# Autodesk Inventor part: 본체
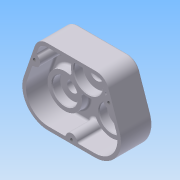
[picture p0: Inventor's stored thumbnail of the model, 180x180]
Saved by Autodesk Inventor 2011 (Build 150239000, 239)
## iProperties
Created: 2014-12
Part Number: 본체
Document SubType Name: Modeling
Designer: SDA24
Density: 2.70923 g/cm^3
Material: 알루미늄-6061
Mass: 613.257 g
Surface Area: 665.191 cm^2
Volume: 226.358 cm^3
Author: SDA24
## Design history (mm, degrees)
sketch "스케치1"
  geometry: L1 (-47, 36)-(47, 36); L2 (0, 46)-(0, -46); L3 (0, 0)-(-32.527, -32.527); L4 (0, 0)-(32.527, -32.527); L5 (-47, 36)-(-66.565, -20.803); L6 (47, 36)-(66.565, -20.803); L7 (-32.527, -68.527)-(32.527, -68.527); A1 r 46 centre (0, 0) between (0, 46) and (0, -46); A2 r 36 centre (-32.527, -32.527) between (-66.565, -20.803) and (-32.527, -68.527); A3 r 36 centre (32.527, -32.527) between (32.527, -68.527) and (66.565, -20.803); 2 further points
  constraints: 14 end point, 8 point on circle, 4 midpoint, 3 centre point, 3 coincident, 2 horizontal, 2 perpendicular, 2 symmetric about line, 2 tangent, 1 point on line, 1 vertical alignment, 2 other
  dimensions: "d1" = 94 distance of L1.start L1.end; "d2" = 36 distance from line of point (0, 0) L1; "d3" = 92 diameter of A1; "d4" = 90 deg angle of L4 L3 (derived); "d5" = 72 diameter of A2
extrude "돌출1" new body sketch "스케치1" distance "d6" = 44; taper "d7" = 0 deg
fillet "모깎기1" dims "d8" = 18
feature "쉘1" dims "d9" = 5
sketch "스케치2"
  geometry: L1 (-27.675, -53.432)-(-12.291, -8.767) reference; L2 (66.689, -94.527)-(1.635, -94.527) reference; L3 (80.615, -8.767)-(95.999, -53.432) reference; L4 (0, 0)-(68.324, 0) reference; L5 (-27.675, -53.432)-(-12.291, -8.767) reference; L6 (66.689, -94.527)-(1.635, -94.527) reference; L7 (80.615, -8.767)-(95.999, -53.432) reference; L8 (0, 0)-(68.324, 0) reference; A1 r 13 centre (0, -13) between (0, 0) and (-12.291, -8.767) reference; A2 r 31 centre (1.635, -63.527) between (-27.675, -53.432) and (1.635, -94.527) reference; A3 r 31 centre (66.689, -63.527) between (66.689, -94.527) and (95.999, -53.432) reference; A4 r 13 centre (68.324, -13) between (80.615, -8.767) and (68.324, 0) reference; A5 r 13 centre (0, -13) between (0, 0) and (-12.291, -8.767) reference; A6 r 31 centre (1.635, -63.527) between (-27.675, -53.432) and (1.635, -94.527) reference; A7 r 31 centre (66.689, -63.527) between (66.689, -94.527) and (95.999, -53.432) reference; A8 r 13 centre (68.324, -13) between (80.615, -8.767) and (68.324, 0) reference; 1 further point
extrude "돌출2" join sketch "스케치2" distance "d10" = 5; taper "d11" = 0 deg
sketch "스케치3"
  geometry: L1 (66.689, -94.527)-(1.635, -94.527) reference; L2 (0, 5)-(68.324, 5) reference; L3 (80.615, -8.767)-(95.999, -53.432) reference; L4 (34.162, 5)-(34.162, -94.527); L5 (66.689, -94.527)-(1.635, -94.527) reference; L6 (-27.675, -53.432)-(-12.291, -8.767) reference; A1 r 8 centre (85.862, -24) between (83.257, -16.436) and (88.467, -31.564); A2 r 8 centre (34.162, -94.527) between (42.162, -94.527) and (26.162, -94.527); A3 r 8 centre (-17.538, -24) between (-20.143, -31.564) and (-14.933, -16.436); 3 further points
  constraints: 10 point on line, 6 point on circle, 3 centre point, 3 midpoint, 2 end point, 1 coincident, 1 vertical
  dimensions: "d12" = 29 distance from line of L2 point (85.862, -24); "d13" = 16 diameter of A1; "d14" = 29 distance from line of L2 A1.centre; "d15" = 16 diameter of A2; "d16" = 16 diameter of A3; "d17" = 29 distance from line of L2 A3.centre
extrude "돌출3" join sketch "스케치3" distance "d18" = 34; taper "d19" = 0 deg
sketch "스케치4"
  geometry: C1 r 24 at (34.162, -31); C2 r 24 at (1.635, -63.527); C3 r 24 at (66.689, -63.527); A1 r 31 centre (1.635, -63.527) between (-27.675, -53.432) and (1.635, -94.527) reference; A2 r 31 centre (66.689, -63.527) between (66.689, -94.527) and (95.999, -53.432) reference; 1 further point
  constraints: 3 centre point, 3 coincident
  dimensions: "d20" = 48 diameter of C1; "d21" = 48 diameter of C2; "d22" = 48 diameter of C3
extrude "돌출4" join sketch "스케치4" distance "d23" = 11; taper "d24" = 0 deg
sketch "스케치5"
  geometry: C1 r 20 at (-32.527, -32.527); C2 r 20 at (32.527, -32.527); A1 r 36 centre (-32.527, -32.527) between (-66.565, -20.803) and (-32.527, -68.527) reference; A2 r 36 centre (32.527, -32.527) between (32.527, -68.527) and (66.565, -20.803) reference; 1 further point
  constraints: 2 centre point, 2 coincident
  dimensions: "d25" = 40 diameter of C1; "d26" = 40 diameter of C2
extrude "돌출5" join sketch "스케치5" distance "d27" = 7; taper "d28" = -10 deg
sketch "스케치6"
  geometry: C1 r 18.766 at (0, 0) reference; C2 r 15 at (0, 0); 1 further point
  constraints: 1 centre point, 1 coincident
  dimensions: "d29" = 30 diameter of C2
extrude "돌출6" cut sketch "스케치6" distance "d30" = 7; taper "d31" = 0 deg
sketch "스케치7"
  geometry: C1 r 15 at (0, 0) reference; C2 r 7.75 at (0, 0); 1 further point
  constraints: 1 centre point, 1 coincident
  dimensions: "d32" = 15.5 diameter of C2
extrude "돌출7" cut sketch "스케치7" distance "d33" = 10; taper "d34" = 0 deg
sketch "스케치8"
  geometry: C1 r 17.5 at (66.689, -63.527); A1 r 24 centre (66.689, -63.527) between (45.578, -52.111) and (55.273, -42.416) reference
  constraints: 1 centre point, 1 coincident
  dimensions: "d35" = 35 diameter of C1
extrude "돌출8" cut sketch "스케치8" distance "d36" = 11; taper "d37" = 0 deg
sketch "스케치9"
  geometry: C1 r 17.5 at (1.635, -63.527); A1 r 24 centre (1.635, -63.527) between (13.051, -42.416) and (22.746, -52.111) reference
  constraints: 1 centre point, 1 coincident
  dimensions: "d38" = 35 diameter of C1
extrude "돌출9" cut sketch "스케치9" distance "d39" = 11; taper "d40" = 0 deg
sketch "스케치10"
  geometry: C1 r 17.5 at (0, 0) reference; C2 r 7.75 at (0, 0); 1 further point
  constraints: 1 centre point, 1 coincident
  dimensions: "d41" = 15.5 diameter of C2
extrude "돌출10" cut sketch "스케치10" distance "d42" = 10; taper "d43" = 0 deg
sketch "스케치11"
  geometry: C1 r 18.766 at (0, 0) reference; C2 r 15 at (0, 0); 1 further point
  constraints: 1 centre point, 1 coincident
  dimensions: "d44" = 30 diameter of C2
extrude "돌출11" cut sketch "스케치11" distance "d45" = 7; taper "d46" = 0 deg
sketch "스케치12"
  geometry: C1 r 20 at (34.162, -31); A1 r 24 centre (34.162, -31) between (22.746, -52.111) and (45.578, -52.111) reference
  constraints: 1 centre point, 1 coincident
  dimensions: "d47" = 40 diameter of C1
extrude "돌출12" cut sketch "스케치12" distance "d48" = 12; taper "d49" = 0 deg
sketch "스케치13"
  geometry: C1 r 20 at (0, 0) reference; C2 r 10 at (0, 0)
  constraints: 1 centre point, 1 coincident
  dimensions: "d50" = 20 diameter of C2
extrude "돌출13" cut sketch "스케치13" distance "d51" = 3; taper "d52" = 0 deg
chamfer "모따기1" distance "d53" = 1; stored, may be unused: second distance "d54" = 3.175, angle "d55" = 45 deg
fillet "모깎기2" dims "d56" = 3
fillet "모깎기3" dims "d57" = 3
fillet "모깎기4" dims "d58" = 3
fillet "모깎기5" dims "d59" = 3
fillet "모깎기6" dims "d60" = 3
fillet "모깎기7" dims "d61" = 3
fillet "모깎기8" dims "d62" = 0.3
fillet "모깎기9" dims "d63" = 0.1
sketch "스케치14"
  geometry: A1 r 8 centre (51.7, 7) between (47.131, 13.567) and (52.144, -0.988) reference; A2 r 8 centre (0, -63.527) between (7.697, -61.345) and (-7.697, -61.345) reference; A3 r 8 centre (-51.7, 7) between (-52.144, -0.988) and (-47.131, 13.567) reference; 4 further points
  constraints: 3 coincident
hole "Hole1" sketch "스케치14" at (-51.7, 7), (0, -63.527), (51.7, 7) diameter "d64" = 4.1402; stored, may be unused: countersink angle "d68" = 82 deg, drill point angle "d70" = 118 deg; dims "d65" = 20, "d66" = 9.525, "d67" = 6.35, "d69" = 23
node "작업 평면1"
sketch "스케치15"
  geometry: L1 (34.162, 36)-(-34.162, 36) reference; 2 further points
  constraints: 1 vertical alignment, 1 other
  dimensions: "d74" = 30 distance from line of L1 point (0, 6)
feature "엠보싱1" sketch "스케치15" dims "d1" = 94, "d2" = 36, "d3" = 92, "d4" = 90 deg (derived), "d5" = 72, "d65" = 20, "d75" = 1, "d76" = 0
fillet "모깎기10" dims "d77" = 0.3
node "솔리드1"
node "투영된 루프1"
other parameters: "d71" = -33.3375
